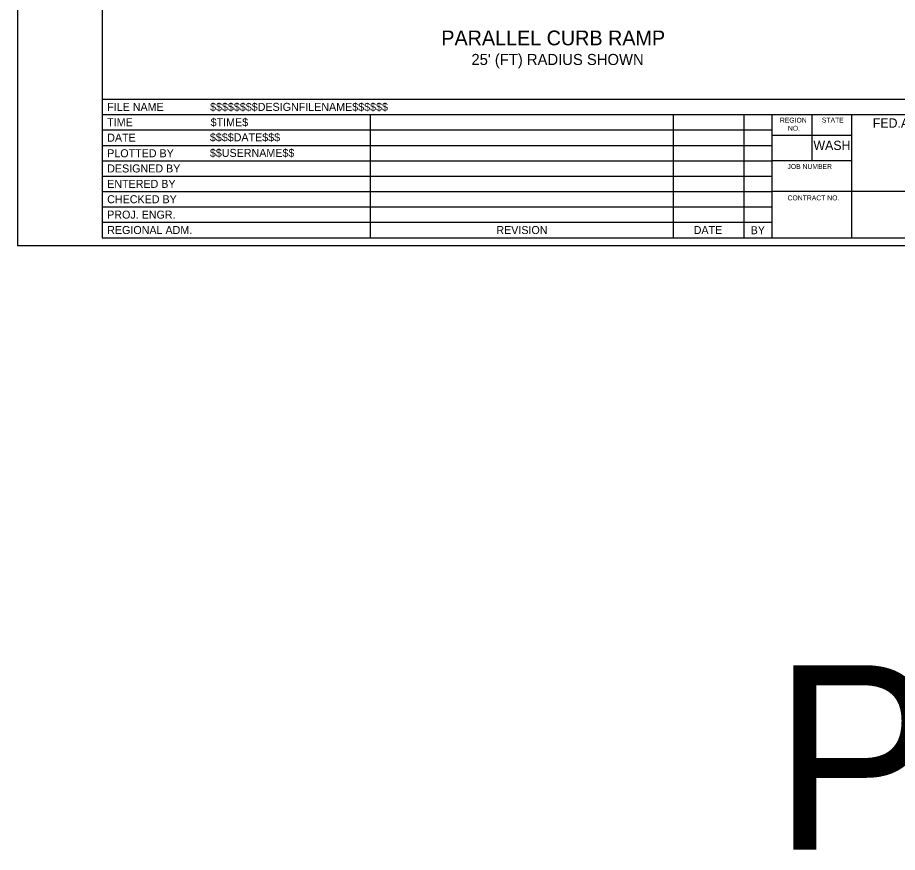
# Model space of a CAD drawing. Extents: x 99988 to 100172, y 99995 to 100047.
# Drawn here: x 99999.31 to 100006.47, y 99995.01 to 100001.79 of the extents above; entities that cross this region are included whole.
import ezdxf

# ---------------------------------------------------------------- set-up
doc = ezdxf.new("R2010")
doc.units = 0
for name, color, linetype in [('Level 20', 7, 'Continuous'), ('SH_GI_PlotLimits', 7, 'Continuous'), ('SH_GI_SheetBorder', 7, 'Continuous'), ('SH_GI_SheetLocationText', 7, 'Continuous'), ('SH_GI_SheetTextInCells', 7, 'Continuous'), ('SH_GI_TitleBlockText', 7, 'Continuous')]:
    doc.layers.add(name, color=color, linetype=linetype)

msp = doc.modelspace()

# ---------------------------------------------------------------- linework, layer by layer
at = {"layer": 'SH_GI_PlotLimits'}
msp.add_lwpolyline([(99999.3125, 99999.9375), (100015.8125, 99999.9375), (100015.8125, 100010.4375), (99999.3125, 100010.4375)], close=True, dxfattribs=at)
at = {"layer": 'SH_GI_SheetBorder'}
for p, q in [((100000, 100010.375), (100000, 100000)), ((100000, 100001.1259), (100015.75, 100001.1259)), ((100000, 100001.0008), (100007.4566, 100001.0008)), ((100002.179, 100001.0008), (100002.179, 100000)), ((100004.641, 100001.0008), (100004.641, 100000)), ((100005.2164, 100001.0008), (100005.2164, 100000)), ((100005.4451, 100001.0008), (100005.4451, 100000)), ((100005.7719, 100000.6255), (100005.7719, 100001.0008)), ((100006.0956, 100000), (100006.0956, 100001.0008)), ((100000, 100000.8757), (100002.1821, 100000.8757)), ((100002.1821, 100000.8757), (100005.4466, 100000.8757)), ((100006.0958, 100000.831), (100005.4466, 100000.831)), ((100000, 100000.7506), (100002.1821, 100000.7506)), ((100002.1821, 100000.7506), (100005.4466, 100000.7506)), ((100000, 100000.6255), (100005.4466, 100000.6255)), ((100006.0958, 100000.6255), (100005.4466, 100000.6255)), ((100000, 100000.5004), (100005.4466, 100000.5004)), ((100000, 100000.3753), (100005.4466, 100000.3753)), ((100007.4566, 100000.3753), (100005.4466, 100000.3753)), ((100000, 100000.2502), (100005.4466, 100000.2502)), ((100000, 100000.1251), (100005.4466, 100000.1251)), ((100000, 100000), (100015.75, 100000))]:
    msp.add_line(p, q, dxfattribs=at)

# ---------------------------------------------------------------- texts
at = {"layer": 'Level 20'}
for s, height, p in [('PARALLEL CURB RAMP', 0.12, (100002.7575, 100001.5634)), ("25' (FT) RADIUS SHOWN", 0.09, (100003.0021, 100001.4034))]:
    msp.add_text(s, height=height, dxfattribs=at).set_placement(p)
at = {"layer": 'SH_GI_SheetLocationText'}
msp.add_text('Plot 1', height=1.5, dxfattribs=at).set_placement((100005.4547, 99995.0267))
at = {"layer": 'SH_GI_SheetTextInCells'}
for s, height, p in [('FILE NAME', 0.06505, (100000.041, 100001.0308)), ('TIME', 0.06505, (100000.041, 100000.9057)), ('REGION', 0.04003, (100005.5099, 100000.9352)), ('STATE', 0.04003, (100005.8511, 100000.9357)), ('FED.AID PROJ.NO.', 0.07506, (100006.2652, 100000.8945)), ('DATE', 0.06505, (100000.041, 100000.7806)), ('NO.', 0.04003, (100005.5752, 100000.869)), ('WASH', 0.07506, (100005.7826, 100000.7131)), ('PLOTTED BY', 0.06505, (100000.041, 100000.6538)), ('DESIGNED BY', 0.065052, (100000.041, 100000.5304)), ('JOB NUMBER', 0.04003, (100005.5712, 100000.5587)), ('ENTERED BY', 0.06505, (100000.041, 100000.4053)), ('CHECKED BY', 0.06505, (100000.041, 100000.2802)), ('CONTRACT NO.', 0.040032, (100005.5725, 100000.3037)), ('PROJ. ENGR.', 0.065052, (100000.041, 100000.1551)), ('REGIONAL ADM.', 0.065052, (100000.041, 100000.03)), ('REVISION', 0.06505, (100003.2048, 100000.03)), ('DATE', 0.06505, (100004.8091, 100000.03)), ('BY', 0.06505, (100005.2725, 100000.0285))]:
    msp.add_text(s, height=height, dxfattribs=at).set_placement(p)
at = {"layer": 'SH_GI_TitleBlockText'}
for s, height, p in [('$$$$$$$$DESIGNFILENAME$$$$$$', 0.065052, (100000.8775, 100001.0308)), ('$TIME$', 0.06505, (100000.882, 100000.9059)), ('$$$$DATE$$$', 0.065052, (100000.8759, 100000.7835)), ('$$USERNAME$$', 0.065052, (100000.8759, 100000.6567))]:
    msp.add_text(s, height=height, dxfattribs=at).set_placement(p)

doc.saveas('drawing.dxf')
